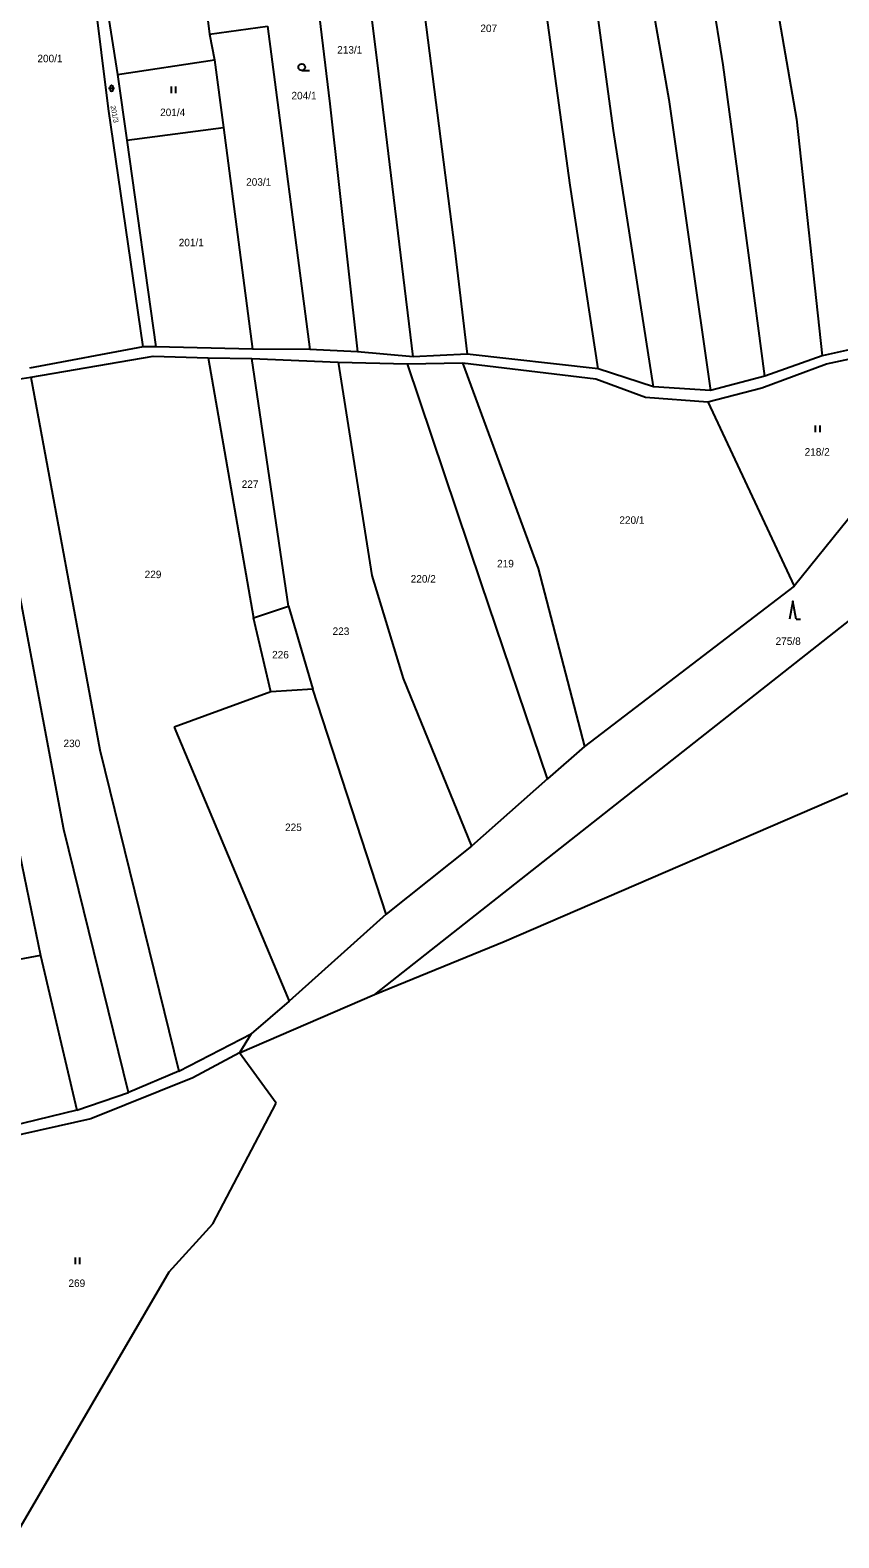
# Model space of a CAD drawing. Extents: x -820420 to -815896, y -1105820 to -1103643.
# Drawn here: x -817392.6 to -817209.6, y -1105260.7 to -1104919.6 of the extents above; entities that cross this region are included whole.
import ezdxf
from ezdxf.enums import TextEntityAlignment as Align

# ---------------------------------------------------------------- set-up
doc = ezdxf.new("R2010")
doc.units = 0
doc.header["$LTSCALE"] = 0.68
doc.layers.add('1', color=7, linetype='Continuous', lineweight=25)
doc.layers.add('3', color=7, linetype='Continuous', lineweight=25)
doc.layers.add('2', color=7, linetype='Continuous')

msp = doc.modelspace()

# ---------------------------------------------------------------- linework, layer by layer
at = {"layer": '1'}
for p, q in [((-817237.78, -1104832.63), (-817219.14, -1104939.69)), ((-817374.92, -1104937.37), (-817386.25, -1104844.67)), ((-817313.7, -1104929.43), (-817324.28, -1104845.05)), ((-817235.75, -1104927.46), (-817244.53, -1104873.02)), ((-817380.49, -1104881.55), (-817372.85, -1104929.63)), ((-817356.77, -1104882.14), (-817352.04, -1104920.46)), ((-817270.42, -1104954.69), (-817278.03, -1104899.26)), ((-817260.57, -1104942.32), (-817265.75, -1104904.36)), ((-817328.67, -1104904.4), (-817324.83, -1104936.23)), ((-817303.68, -1104913.59), (-817296.58, -1104968.84)), ((-817251.64, -1104914.68), (-817248.06, -1104935.25)), ((-817352.04, -1104920.46), (-817338.91, -1104918.67)), ((-817352.04, -1104920.46), (-817350.94, -1104926.33)), ((-817338.91, -1104918.67), (-817329.34, -1104991.82)), ((-817372.85, -1104929.63), (-817350.94, -1104926.33)), ((-817350.94, -1104926.33), (-817348.84, -1104941.57)), ((-817230.03, -1104969.99), (-817235.75, -1104927.46)), ((-817372.85, -1104929.63), (-817370.75, -1104944.51)), ((-817305.9, -1104993.49), (-817313.7, -1104929.43)), ((-817367.04, -1104991.22), (-817374.92, -1104937.37)), ((-817324.83, -1104936.23), (-817318.54, -1104992.35)), ((-817248.06, -1104935.25), (-817238.6, -1105001.08)), ((-817370.75, -1104944.51), (-817348.84, -1104941.57)), ((-817348.84, -1104941.57), (-817342.27, -1104991.74)), ((-817219.14, -1104939.69), (-817213.37, -1104993.27)), ((-817370.75, -1104944.51), (-817364.15, -1104991.26)), ((-817251.49, -1105000.28), (-817260.57, -1104942.32)), ((-817264.04, -1104996.19), (-817270.42, -1104954.69)), ((-817296.58, -1104968.84), (-817293.73, -1104992.9)), ((-817226.3, -1104997.89), (-817230.03, -1104969.99)), ((-817192.66, -1104988.66), (-817213.37, -1104993.27)), ((-817367.04, -1104991.22), (-817392.8, -1104996.09)), ((-817364.15, -1104991.26), (-817367.04, -1104991.22)), ((-817342.27, -1104991.74), (-817364.15, -1104991.26)), ((-817329.34, -1104991.82), (-817342.27, -1104991.74)), ((-817318.54, -1104992.35), (-817329.34, -1104991.82)), ((-817305.9, -1104993.49), (-817318.54, -1104992.35)), ((-817293.73, -1104992.9), (-817305.9, -1104993.49)), ((-817264.04, -1104996.19), (-817293.73, -1104992.9)), ((-817212.34, -1104995.09), (-817193.25, -1104990.98)), ((-817392.48, -1104998.11), (-817364.78, -1104993.36)), ((-817364.78, -1104993.36), (-817352.35, -1104993.7)), ((-817352.35, -1104993.7), (-817342.42, -1104993.84)), ((-817352.35, -1104993.7), (-817342.04, -1105052.59)), ((-817342.42, -1104993.84), (-817322.91, -1104994.72)), ((-817334.18, -1105049.93), (-817342.42, -1104993.84)), ((-817322.91, -1104994.72), (-817315.26, -1105042.99)), ((-817322.91, -1104994.72), (-817307.21, -1104995.08)), ((-817307.21, -1104995.08), (-817294.73, -1104994.89)), ((-817290.52, -1105044.62), (-817307.21, -1104995.08)), ((-817294.73, -1104994.89), (-817264.57, -1104998.47)), ((-817294.73, -1104994.89), (-817277.62, -1105041.39)), ((-817251.49, -1105000.28), (-817264.04, -1104996.19)), ((-817227.02, -1105000.54), (-817212.34, -1104995.09)), ((-817213.37, -1104993.27), (-817226.3, -1104997.89)), ((-817403.55, -1104999.82), (-817392.48, -1104998.11)), ((-817392.48, -1104998.11), (-817376.88, -1105082.43)), ((-817264.57, -1104998.47), (-817253.34, -1105002.6)), ((-817226.3, -1104997.89), (-817238.6, -1105001.08)), ((-817143.46, -1105002.85), (-817314.7, -1105137.81)), ((-817253.34, -1105002.6), (-817239.26, -1105003.7)), ((-817238.6, -1105001.08), (-817251.49, -1105000.28)), ((-817239.26, -1105003.7), (-817227.02, -1105000.54)), ((-817239.26, -1105003.7), (-817219.66, -1105045.37)), ((-817207.39, -1105030.12), (-817219.66, -1105045.37)), ((-817385.02, -1105100.44), (-817396.96, -1105037.03)), ((-817315.26, -1105042.99), (-817308.23, -1105066.25)), ((-817277.62, -1105041.39), (-817267.11, -1105081.64)), ((-817407.13, -1105047.39), (-817390.32, -1105128.96)), ((-817275.51, -1105088.96), (-817290.52, -1105044.62)), ((-817219.66, -1105045.37), (-817267.11, -1105081.64)), ((-817342.04, -1105052.59), (-817334.18, -1105049.93)), ((-817334.18, -1105049.93), (-817328.64, -1105068.67)), ((-817338.16, -1105069.29), (-817342.04, -1105052.59)), ((-817308.23, -1105066.25), (-817292.72, -1105104.21)), ((-817338.16, -1105069.29), (-817360.04, -1105077.28)), ((-817328.64, -1105068.67), (-817338.16, -1105069.29)), ((-817312.02, -1105119.59), (-817328.64, -1105068.67)), ((-817360.04, -1105077.28), (-817333.98, -1105139.33)), ((-817267.11, -1105081.64), (-817275.51, -1105088.96)), ((-817376.88, -1105082.43), (-817358.99, -1105155.15)), ((-817285.31, -1105125.76), (-817196.91, -1105087.63)), ((-817275.51, -1105088.96), (-817292.72, -1105104.21)), ((-817370.4, -1105159.93), (-817385.02, -1105100.44)), ((-817292.72, -1105104.21), (-817312.02, -1105119.59)), ((-817312.02, -1105119.59), (-817333.98, -1105139.33)), ((-817314.7, -1105137.81), (-817285.31, -1105125.76)), ((-817390.32, -1105128.96), (-817414.16, -1105133.48)), ((-817345.25, -1105151.01), (-817314.7, -1105137.81)), ((-817333.98, -1105139.33), (-817342.61, -1105146.68)), ((-817358.99, -1105155.15), (-817342.61, -1105146.68)), ((-817342.61, -1105146.68), (-817345.25, -1105151.01)), ((-817345.25, -1105151.01), (-817355.83, -1105156.61)), ((-817336.95, -1105162.36), (-817345.25, -1105151.01)), ((-817355.83, -1105156.61), (-817378.9, -1105165.91)), ((-817358.99, -1105155.15), (-817370.4, -1105159.93)), ((-817351.3, -1105189.67), (-817336.95, -1105162.36)), ((-817382.1, -1105163.92), (-817404.3, -1105169.4)), ((-817378.9, -1105165.91), (-817398.08, -1105170.21)), ((-817361.19, -1105200.55), (-817351.3, -1105189.67)), ((-817396.24, -1105260.73), (-817361.19, -1105200.55))]:
    msp.add_line(p, q, dxfattribs=at)
msp.add_lwpolyline([(-817390.32, -1105128.96), (-817382.1, -1105163.92), (-817370.4, -1105159.93)], dxfattribs=at)
at = {"layer": '3'}
for p, q in [((-817331.163, -1104928.7), (-817329.413, -1104928.7)), ((-817374.871, -1104932.721), (-817373.529, -1104932.721)), ((-817374.535, -1104932.385), (-817374.535, -1104933.056)), ((-817373.865, -1104933.056), (-817373.865, -1104932.385)), ((-817360.641, -1104933.84), (-817360.641, -1104932.34)), ((-817359.64, -1104933.84), (-817359.64, -1104932.34)), ((-817214.831, -1105010.51), (-817214.831, -1105009.01)), ((-817213.83, -1105010.51), (-817213.83, -1105009.01)), ((-817219.26, -1105052.82), (-817218.264, -1105052.82)), ((-817382.391, -1105198.79), (-817382.391, -1105197.29)), ((-817381.39, -1105198.79), (-817381.39, -1105197.29))]:
    msp.add_line(p, q, dxfattribs=at)
msp.add_lwpolyline([(-817219.26, -1105052.82), (-817220.01, -1105048.82), (-817220.76, -1105052.82)], dxfattribs=at)
msp.add_circle((-817331.1629, -1104927.9498), 0.75, dxfattribs=at)
for centre, start, end in [((-817374.2, -1104932.3856), 0, 180), ((-817374.2, -1104933.0556), 180, 359.98789)]:
    msp.add_arc(centre, 0.335, start, end, dxfattribs=at)

# ---------------------------------------------------------------- texts
at = {"layer": '2'}
for s, p in [('207', (-817288.819, -1104920.015)), ('213/1', (-817320.29, -1104924.885)), ('200/1', (-817388.15, -1104926.845)), ('204/1', (-817330.64, -1104935.235)), ('201/4', (-817360.37, -1104939.025)), ('203/1', (-817340.9, -1104954.785)), ('201/1', (-817356.16, -1104968.485)), ('218/2', (-817214.47, -1105015.865)), ('227', (-817342.849, -1105023.165)), ('220/1', (-817256.41, -1105031.285)), ('219', (-817285.039, -1105041.135)), ('229', (-817364.819, -1105043.575)), ('220/2', (-817303.65, -1105044.585)), ('223', (-817322.279, -1105056.435)), ('275/8', (-817221.04, -1105058.685)), ('226', (-817335.969, -1105061.745)), ('230', (-817383.189, -1105081.815)), ('225', (-817333.039, -1105100.805)), ('269', (-817382.069, -1105203.965))]:
    msp.add_text(s, height=1.7, dxfattribs=at).set_placement(p, align=Align.CENTER)
msp.add_text('201/3', height=1.14, rotation=281, dxfattribs=at).set_placement((-817374.0784, -1104938.6792), align=Align.CENTER)

doc.saveas('drawing.dxf')
